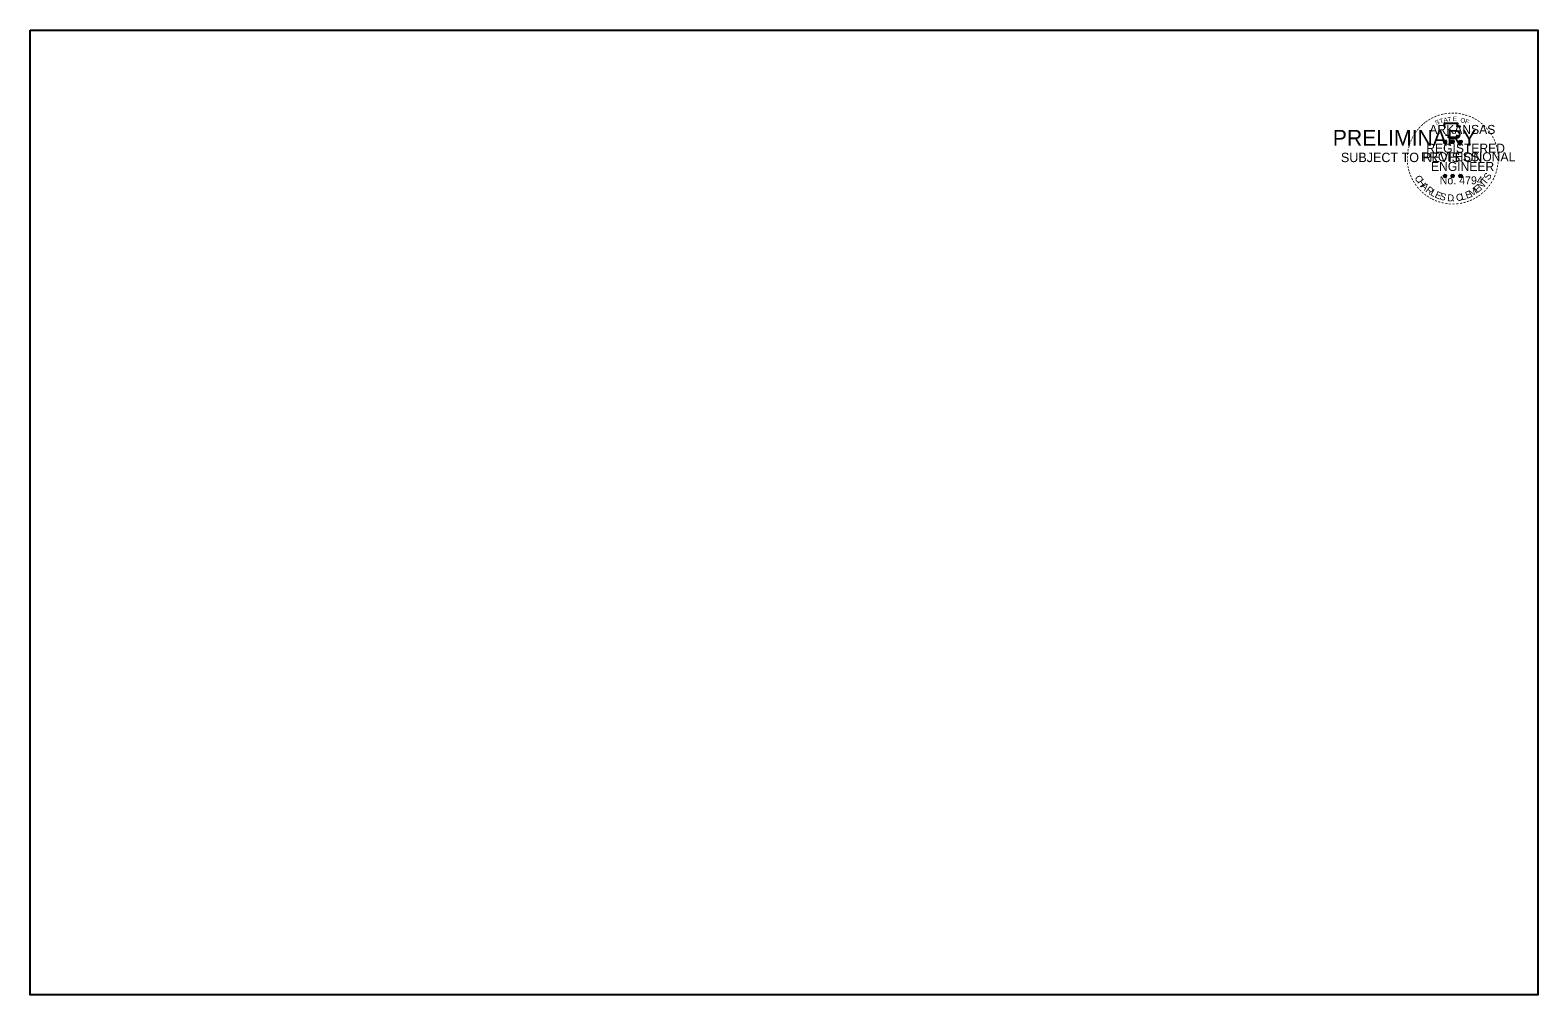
# Model space of a CAD drawing. Extents: x 9844 to 18514, y 8651 to 12569.
# Drawn here: x 16848 to 18514, y 11502 to 12569 of the extents above; entities that cross this region are included whole.
import ezdxf

# ---------------------------------------------------------------- set-up
doc = ezdxf.new("R2010")
doc.units = 0
for name, color, linetype in [('STAMP_PE_CRAFTON-SIGNATURE', 7, 'Continuous'), ('STAMP_PE_SEAL-INFO', 7, 'Continuous'), ('STAMP_PE_TXT', 7, 'Continuous')]:
    doc.layers.add(name, color=color, linetype=linetype)

msp = doc.modelspace()

# ---------------------------------------------------------------- linework, layer by layer
at = {"layer": 'STAMP_PE_SEAL-INFO'}
msp.add_lwpolyline([(16847.7, 12569), (18514.4, 12569), (18514.4, 11502.3), (16847.7, 11502.3)], close=True, dxfattribs=at)
at = {"layer": 'STAMP_PE_TXT'}
for p, q in [((18410, 12446.3), (18411.8, 12445.7)), ((18410, 12446.3), (18411.3, 12446.1)), ((18410, 12446.3), (18411.2, 12445.7)), ((18410.7, 12444.2), (18411.8, 12445.7)), ((18410.7, 12444.2), (18411.3, 12445.5)), ((18410.7, 12444.2), (18411.8, 12445.3)), ((18411.8, 12447.6), (18411.6, 12446.3)), ((18411.8, 12445.7), (18411.8, 12447.6)), ((18411.8, 12447.6), (18412, 12446.3)), ((18413.5, 12446.3), (18411.8, 12445.7)), ((18412.9, 12444.2), (18411.8, 12445.7)), ((18412.9, 12444.2), (18411.8, 12445.3)), ((18413.5, 12446.3), (18412.1, 12446)), ((18412.9, 12444.2), (18412.2, 12445.7)), ((18413.5, 12446.3), (18412.5, 12445.8)), ((18418.4, 12446.3), (18420.1, 12445.7)), ((18418.4, 12446.3), (18419.7, 12446.1)), ((18418.4, 12446.3), (18419.6, 12445.7)), ((18419.1, 12444.2), (18420.1, 12445.7)), ((18419.1, 12444.2), (18419.7, 12445.5)), ((18419.1, 12444.2), (18420.1, 12445.3)), ((18420.1, 12447.6), (18419.9, 12446.3)), ((18420.1, 12445.7), (18420.1, 12447.6)), ((18420.1, 12447.6), (18420.4, 12446.3)), ((18421.9, 12446.3), (18420.1, 12445.7)), ((18421.2, 12444.2), (18420.1, 12445.7)), ((18421.2, 12444.2), (18420.1, 12445.3)), ((18421.9, 12446.3), (18420.4, 12446)), ((18421.2, 12444.2), (18420.5, 12445.7)), ((18421.9, 12446.3), (18420.9, 12445.8)), ((18427.2, 12446.2), (18429, 12445.7)), ((18427.2, 12446.2), (18428.5, 12446)), ((18427.2, 12446.2), (18428.4, 12445.6)), ((18427.9, 12444.2), (18429, 12445.7)), ((18427.9, 12444.2), (18428.5, 12445.4)), ((18427.9, 12444.2), (18429, 12445.3)), ((18429, 12447.5), (18428.8, 12446.2)), ((18429, 12445.7), (18429, 12447.5)), ((18429, 12447.5), (18429.2, 12446.2)), ((18430.7, 12446.2), (18429, 12445.7)), ((18430, 12444.2), (18429, 12445.7)), ((18430, 12444.2), (18429, 12445.3)), ((18430.7, 12446.2), (18429.3, 12446)), ((18430, 12444.2), (18429.3, 12445.6)), ((18430.7, 12446.2), (18429.7, 12445.7)), ((18410, 12408.4), (18411.8, 12407.9)), ((18410, 12408.4), (18411.3, 12408.2)), ((18410, 12408.4), (18411.2, 12407.8)), ((18410.7, 12406.4), (18411.8, 12407.9)), ((18410.7, 12406.4), (18411.3, 12407.6)), ((18410.7, 12406.4), (18411.8, 12407.5)), ((18411.8, 12409.7), (18411.6, 12408.4)), ((18411.8, 12407.9), (18411.8, 12409.7)), ((18411.8, 12409.7), (18412, 12408.4)), ((18413.5, 12408.4), (18411.8, 12407.9)), ((18412.8, 12406.4), (18411.8, 12407.9)), ((18412.8, 12406.4), (18411.8, 12407.4)), ((18413.5, 12408.4), (18412.1, 12408.2)), ((18412.8, 12406.4), (18412.2, 12407.8)), ((18413.5, 12408.4), (18412.5, 12407.9)), ((18418.4, 12408.4), (18420.1, 12407.9)), ((18418.4, 12408.4), (18419.6, 12408.2)), ((18418.4, 12408.4), (18419.6, 12407.8)), ((18419, 12406.4), (18420.1, 12407.9)), ((18419, 12406.4), (18419.7, 12407.6)), ((18419, 12406.4), (18420.1, 12407.5)), ((18420.1, 12409.7), (18419.9, 12408.4)), ((18420.1, 12407.9), (18420.1, 12409.7)), ((18420.1, 12409.7), (18420.4, 12408.4)), ((18421.9, 12408.4), (18420.1, 12407.9)), ((18421.2, 12406.4), (18420.1, 12407.9)), ((18421.2, 12406.4), (18420.1, 12407.4)), ((18421.9, 12408.4), (18420.4, 12408.2)), ((18421.2, 12406.4), (18420.5, 12407.8)), ((18421.9, 12408.4), (18420.8, 12407.9)), ((18427.2, 12408.4), (18429, 12407.8)), ((18427.2, 12408.4), (18428.5, 12408.1)), ((18427.2, 12408.4), (18428.4, 12407.8)), ((18427.9, 12406.3), (18429, 12407.8)), ((18427.9, 12406.3), (18428.5, 12407.5)), ((18427.9, 12406.3), (18428.9, 12407.4)), ((18429, 12409.6), (18428.7, 12408.4)), ((18430, 12406.3), (18428.9, 12407.4)), ((18429, 12407.8), (18429, 12409.6)), ((18429, 12409.6), (18429.2, 12408.4)), ((18430.7, 12408.4), (18429, 12407.8)), ((18430, 12406.3), (18429, 12407.8)), ((18430.7, 12408.4), (18429.3, 12408.1)), ((18430, 12406.3), (18429.3, 12407.8)), ((18430.7, 12408.4), (18429.7, 12407.9))]:
    msp.add_line(p, q, dxfattribs=at)
for points in [[(18410.3, 12465.7), (18411.6, 12461.5)], [(18427.8, 12461.1), (18428.5, 12462.5), (18425.1, 12462.4), (18425.8, 12465.7), (18410.3, 12465.7)], [(18412.7, 12453.6), (18412.7, 12453.1), (18415.5, 12453), (18415.3, 12450.7), (18424.6, 12450.7), (18425.6, 12453.3)], [(18411.8, 12447.6), (18412.9, 12444.2), (18410, 12446.3), (18413.5, 12446.3), (18410.7, 12444.2), (18411.8, 12447.6)], [(18420.1, 12447.6), (18421.2, 12444.2), (18418.4, 12446.3), (18421.9, 12446.3), (18419.1, 12444.2), (18420.1, 12447.6)], [(18429, 12447.5), (18430, 12444.2), (18427.2, 12446.2), (18430.7, 12446.2), (18427.9, 12444.2), (18429, 12447.5)], [(18411.8, 12409.7), (18412.8, 12406.4), (18410, 12408.4), (18413.5, 12408.4), (18410.7, 12406.4), (18411.8, 12409.7)], [(18420.1, 12409.7), (18421.2, 12406.4), (18418.4, 12408.4), (18421.9, 12408.4), (18419, 12406.4), (18420.1, 12409.7)], [(18429, 12409.6), (18430, 12406.3), (18427.2, 12408.4), (18430.7, 12408.4), (18427.9, 12406.3), (18429, 12409.6)]]:
    msp.add_lwpolyline(points, dxfattribs=at)
for centre, radius in [((18411.8, 12445.7), 0.861), ((18411.8, 12445.7), 0.723), ((18411.8, 12445.7), 0.579), ((18411.8, 12445.7), 0.495), ((18411.8, 12445.7), 0.374), ((18411.8, 12445.7), 0.248), ((18411.8, 12445.7), 0.148), ((18420.1, 12445.7), 0.861), ((18420.1, 12445.7), 0.723), ((18420.1, 12445.7), 0.579), ((18420.1, 12445.7), 0.495), ((18420.1, 12445.7), 0.374), ((18420.1, 12445.7), 0.248), ((18420.1, 12445.7), 0.148), ((18429, 12445.7), 0.861), ((18429, 12445.7), 0.723), ((18429, 12445.7), 0.579), ((18429, 12445.7), 0.495), ((18429, 12445.7), 0.374), ((18429, 12445.7), 0.248), ((18429, 12445.7), 0.148), ((18411.8, 12407.9), 0.861), ((18411.8, 12407.9), 0.723), ((18411.8, 12407.9), 0.579), ((18411.8, 12407.9), 0.495), ((18411.8, 12407.9), 0.374), ((18411.8, 12407.9), 0.248), ((18411.8, 12407.9), 0.148), ((18420.1, 12407.9), 0.861), ((18420.1, 12407.9), 0.723), ((18420.1, 12407.9), 0.579), ((18420.1, 12407.9), 0.495), ((18420.1, 12407.9), 0.374), ((18420.1, 12407.9), 0.248), ((18420.1, 12407.9), 0.148), ((18428.9, 12407.8), 0.861), ((18428.9, 12407.8), 0.723), ((18428.9, 12407.8), 0.579), ((18428.9, 12407.8), 0.495), ((18428.9, 12407.8), 0.374), ((18428.9, 12407.8), 0.248), ((18428.9, 12407.8), 0.148)]:
    msp.add_circle(centre, radius, dxfattribs=at)

# ---------------------------------------------------------------- texts
at = {"layer": 'STAMP_PE_CRAFTON-SIGNATURE'}
for s, height, p in [('PRELIMINARY', 17.5, (18287.7, 12441.2)), ('SUBJECT TO REVISION', 10.376, (18296.7, 12423.1))]:
    msp.add_text(s, height=height, dxfattribs=at).set_placement(p)
at = {"layer": 'STAMP_PE_TXT'}
for s, height, rotation, p in [('-', 8, 38.9507, (18389.4, 12462.7)), ('-', 8, 36.2317, (18391.8, 12464.6)), ('-', 8, 34.0636, (18394.7, 12466.5)), ('-', 8, 28.7918, (18397.7, 12468.4)), ('-', 8, 24.3072, (18400.8, 12470)), ('S', 5, 21.594, (18402, 12464.1)), ('-', 8, 19.1761, (18404, 12471.3)), ('T', 5, 16.4036, (18406.6, 12465.7)), ('-', 8, 13.6302, (18407.7, 12472.5)), ('A', 5, 11.2132, (18410.7, 12467)), ('-', 8, 10.2193, (18411.1, 12473.3)), ('T', 5, 6.0228, (18415, 12467.8)), ('-', 8, 5.8968, (18414.8, 12473.9)), ('-', 8, 0.1862, (18418.6, 12474.2)), ('E', 5, 0.8323, (18420.5, 12468.4)), ('-', 8, 357.743, (18422.3, 12474.2)), ('-', 8, 352.1617, (18426, 12473.9)), ('O', 5, 350.4515, (18428.5, 12467.3)), ('-', 8, 347.2049, (18429.6, 12473.3)), ('F', 5, 340.0707, (18433.3, 12466.2)), ('-', 8, 342.3362, (18432.7, 12472.5)), ('-', 8, 337.8551, (18436.4, 12471.4)), ('-', 8, 334.1211, (18439.6, 12470.1)), ('-', 8, 329.6409, (18442.5, 12468.7)), ('-', 8, 325.8627, (18445.7, 12466.9)), ('-', 8, 320.5297, (18448.7, 12464.7)), ('-', 8, 62.8713, (18377.7, 12447.2)), ('-', 8, 58.0706, (18379.3, 12450.3)), ('-', 8, 54.2325, (18380.9, 12452.9)), ('-', 8, 50.6142, (18383, 12455.8)), ('-', 8, 48.4231, (18385, 12458.2)), ('-', 8, 42.9622, (18387.2, 12460.6)), ('-', 8, 315.5786, (18451.7, 12462.3)), ('-', 8, 309.8797, (18454.6, 12459.5)), ('-', 8, 306.6522, (18457.2, 12456.5)), ('-', 7, 303.6753, (18459.6, 12453.7)), ('-', 8, 299.6684, (18461.2, 12450.6)), ('-', 8, 85.1863, (18373.3, 12430.4)), ('-', 8, 81.2013, (18373.7, 12433.9)), ('-', 8, 75.461, (18374.4, 12437.4)), ('-', 8, 72.3945, (18375.3, 12441)), ('-', 8, 67.7743, (18376.4, 12444.2)), ('-', 8, 294.6628, (18462.8, 12447.6)), ('-', 8, 290.5728, (18464.1, 12444.7)), ('-', 8, 285.1233, (18465.3, 12441.8)), ('-', 8, 280.5493, (18466.3, 12438.1)), ('-', 8, 276.5962, (18467.1, 12434.3)), ('-', 8, 94.1959, (18373.4, 12423.3)), ('-', 8, 89.0622, (18373.2, 12426.9)), ('-', 8, 98.9479, (18373.7, 12420)), ('-', 8, 101.7149, (18374.4, 12416.3)), ('-', 8, 260.9953, (18467.1, 12420.9)), ('-', 8, 263.5172, (18467.5, 12424.2)), ('-', 8, 274.3301, (18467.4, 12430.6)), ('-', 8, 269.9407, (18467.6, 12427.5)), ('-', 8, 105.4578, (18375.2, 12413.3)), ('-', 8, 109.0874, (18376.3, 12410.2)), ('-', 8, 114.0643, (18377.6, 12407.2)), ('-', 8, 115.7289, (18379.1, 12404.1)), ('-', 8, 120.4471, (18380.9, 12401.2)), ('C', 7.7, 296.9133, (18377.9, 12406.1)), ('H', 7.7, 303.2799, (18380.9, 12400.9)), ('N', 7.7, 45.1449, (18451.8, 12392.1)), ('T', 7.7, 51.5114, (18456.6, 12397.3)), ('S', 7.7, 57.878, (18460.2, 12402.5)), ('-', 8, 239.0712, (18461.3, 12403.6)), ('-', 8, 244.6197, (18463.2, 12407.4)), ('-', 8, 247.8887, (18464.6, 12410.5)), ('-', 8, 255.7626, (18465.6, 12414.1)), ('-', 8, 255.7626, (18466.6, 12417.5)), ('-', 8, 125.8934, (18382.9, 12398.4)), ('-', 8, 130.7181, (18385.2, 12395.6)), ('-', 8, 134.2238, (18387.8, 12392.9)), ('A', 7.7, 316.013, (18384.5, 12395.8)), ('-', 8, 138.9338, (18390.4, 12390.6)), ('-', 8, 144.6463, (18393.2, 12388.5)), ('R', 7.7, 322.3796, (18389.6, 12390.9)), ('-', 8, 148.0898, (18396, 12386.7)), ('-', 8, 151.5704, (18398.9, 12385)), ('L', 7.7, 328.7461, (18394.8, 12387.2)), ('E', 7.7, 335.1127, (18399.8, 12384.4)), ('S', 7.7, 341.4792, (18405.1, 12382.2)), ('D', 7.7, 354.2124, (18414, 12380.1)), ('C', 7.7, 6.9455, (18424.4, 12379.9)), ('L', 7.7, 13.3121, (18430.3, 12380.9)), ('E', 7.7, 19.6786, (18435.8, 12382.5)), ('M', 7.7, 32.4117, (18440.9, 12384.4)), ('E', 7.7, 38.7783, (18447.3, 12388.5)), ('-', 8, 212.2491, (18446.7, 12387.9)), ('-', 8, 215.7363, (18449.4, 12389.8)), ('-', 8, 221.0851, (18452.1, 12392.2)), ('-', 8, 225.7653, (18454.7, 12394.7)), ('-', 8, 231.2538, (18457.1, 12397.5)), ('-', 8, 233.8452, (18459.3, 12400.4)), ('-', 8, 154.6002, (18401.5, 12383.8)), ('-', 8, 158.5612, (18404.6, 12382.5)), ('-', 8, 162.7983, (18408, 12381.5)), ('-', 8, 167.5555, (18411.6, 12380.7)), ('-', 8, 173.1155, (18415.5, 12380.1)), ('-', 8, 176.5183, (18419.2, 12379.8)), ('-', 8, 181.5918, (18422.9, 12379.9)), ('.', 7.7, 0.5789, (18419.8, 12379.8)), ('-', 8, 185.8167, (18427, 12380.3)), ('-', 8, 191.2858, (18430.7, 12381)), ('-', 8, 195.4743, (18434.3, 12382)), ('-', 8, 200.7184, (18437.7, 12383.2)), ('-', 8, 204.2516, (18440.8, 12384.5)), ('-', 8, 207.3568, (18443.9, 12386.1))]:
    msp.add_text(s, height=height, rotation=rotation, dxfattribs=at).set_placement(p)
for s, height, p in [('ARKANSAS', 10, (18394.5, 12454.2)), ('PROFESSIONAL', 10, (18385.4, 12424)), ('REGISTERED', 10, (18391.1, 12433.5)), ('ENGINEER', 10, (18396.3, 12413.3)), ('No. 4794', 8.78, (18405.9, 12398.6))]:
    msp.add_text(s, height=height, dxfattribs=at).set_placement(p)

doc.saveas('drawing.dxf')
